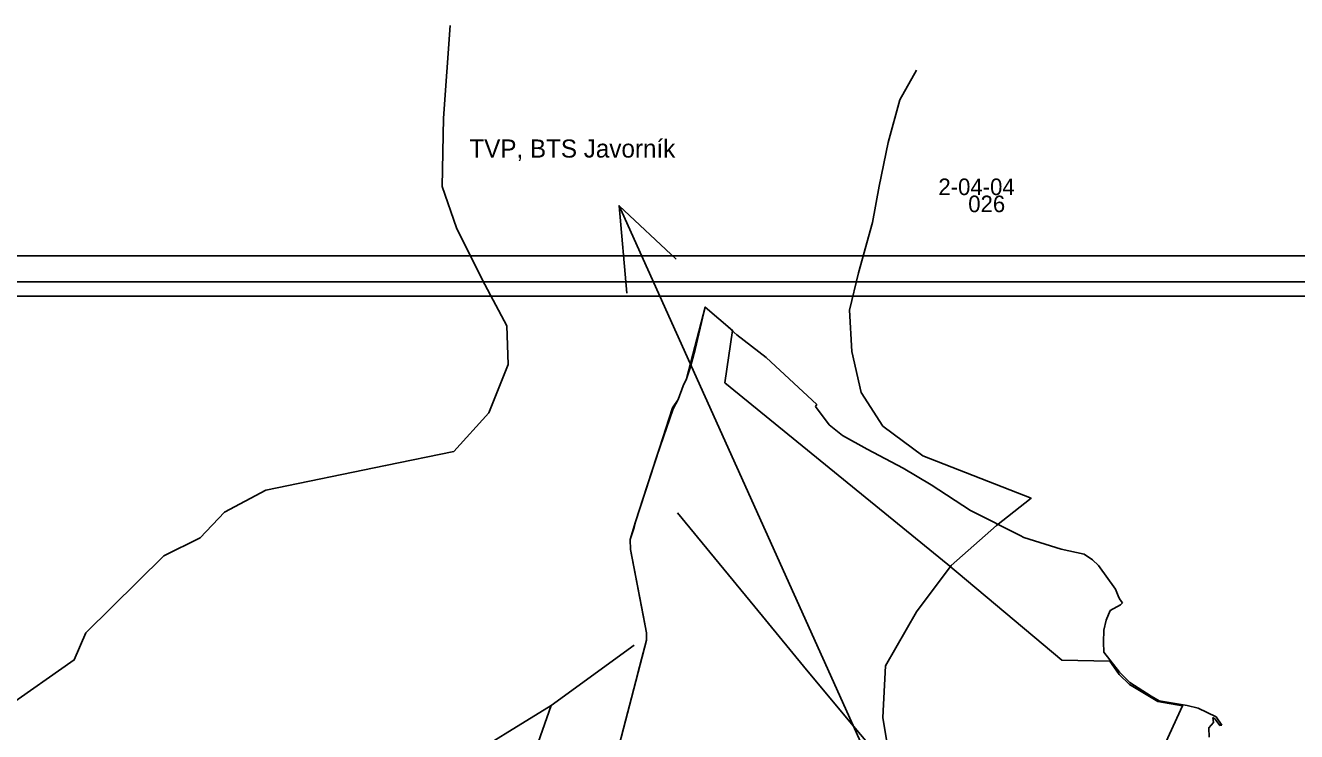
# Model space of a CAD drawing. Extents: x -557103 to -548162, y -1041918 to -1033974.
# Drawn here: x -554667 to -552210, y -1035524 to -1034159 of the extents above; entities that cross this region are included whole.
import ezdxf

# ---------------------------------------------------------------- set-up
doc = ezdxf.new("R2010")
doc.units = 0
for name, color, linetype in [('body1', 7, 'Continuous'), ('body3', 7, 'Continuous'), ('Rámeček', 7, 'Continuous'), ('Vrstva 12', 7, 'Continuous'), ('Vrstva 14', 7, 'Continuous'), ('Vrstva 15', 7, 'Continuous'), ('Vrstva 16', 7, 'Continuous'), ('Vrstva 63', 7, 'Continuous'), ('Vrstva 9', 7, 'Continuous')]:
    doc.layers.add(name, color=color, linetype=linetype)

msp = doc.modelspace()

# ---------------------------------------------------------------- linework, layer by layer
at = {"layer": 'body1'}
msp.add_lwpolyline([(-550469.3, -1040018.6), (-555211.6, -1040018.6), (-555211.6, -1034654.7), (-550469.3, -1034654.7)], close=True, dxfattribs=at)
at = {"layer": 'body3'}
for p, q in [((-553352.9, -1034702.9), (-553372.3, -1034785.2)), ((-553292, -1034757.1), (-553352.9, -1034702.9)), ((-553235.4, -1034801), (-553292, -1034757.1)), ((-553372.3, -1034785.2), (-553381.7, -1034818.7)), ((-553137.6, -1034891.8), (-553235.4, -1034801)), ((-553381.7, -1034818.7), (-553389.1, -1034842)), ((-553389.1, -1034842), (-553395.8, -1034855.3)), ((-553395.8, -1034855.3), (-553405.4, -1034882.1)), ((-553416.1, -1034897.8), (-553441.4, -1034976.1)), ((-553405.4, -1034882.1), (-553416.1, -1034897.8)), ((-553139.7, -1034895.2), (-553137.6, -1034891.8)), ((-553113.8, -1034931.1), (-553139.7, -1034895.2)), ((-553088, -1034951.8), (-553113.8, -1034931.1)), ((-553040.2, -1034977.8), (-553088, -1034951.8)), ((-553441.4, -1034976.1), (-553487.7, -1035118.7)), ((-552970.6, -1035014.9), (-553040.2, -1034977.8)), ((-552916.4, -1035047.1), (-552970.6, -1035014.9)), ((-552840.6, -1035096.7), (-552916.4, -1035047.1)), ((-552741.6, -1035146.3), (-552840.6, -1035096.7)), ((-553487.7, -1035118.7), (-553490.7, -1035129.1)), ((-553490.7, -1035129.1), (-553497.9, -1035152.3)), ((-552739.5, -1035147.3), (-552741.6, -1035146.3)), ((-552737.1, -1035148.6), (-552739.5, -1035147.3)), ((-552665, -1035171.2), (-552737.1, -1035148.6)), ((-553497.9, -1035152.3), (-553497.8, -1035171.9)), ((-553497.8, -1035171.9), (-553466.6, -1035332.8)), ((-552620.8, -1035181), (-552665, -1035171.2)), ((-552604.2, -1035191.8), (-552620.8, -1035181)), ((-552592.7, -1035202.9), (-552604.2, -1035191.8)), ((-552560, -1035248.3), (-552592.7, -1035202.9)), ((-552553.3, -1035264.8), (-552560, -1035248.3)), ((-552551.3, -1035269.1), (-552553.3, -1035264.8)), ((-552546.5, -1035274.7), (-552551.3, -1035269.1)), ((-552577.8, -1035308.7), (-552570.4, -1035290.1)), ((-552570.4, -1035290.1), (-552550.7, -1035278.7)), ((-552550.7, -1035278.7), (-552546.5, -1035274.7)), ((-552582.5, -1035328.1), (-552577.8, -1035308.7)), ((-553466.6, -1035332.8), (-553466.8, -1035347.5)), ((-552583.3, -1035350.9), (-552582.5, -1035328.1)), ((-553466.8, -1035347.5), (-553499.5, -1035473.7)), ((-552582.3, -1035370.7), (-552583.3, -1035350.9)), ((-552552.5, -1035408.8), (-552582.3, -1035370.7)), ((-552532.6, -1035429.3), (-552552.5, -1035408.8)), ((-552491.1, -1035455.5), (-552532.6, -1035429.3)), ((-552475.8, -1035464.2), (-552491.1, -1035455.5)), ((-552421.6, -1035473.8), (-552475.8, -1035464.2)), ((-553499.5, -1035473.7), (-553532.1, -1035599.9)), ((-552400.4, -1035478.6), (-552421.6, -1035473.8)), ((-552365.2, -1035495.4), (-552400.4, -1035478.6)), ((-552379.4, -1035516.6), (-552370.7, -1035506.3)), ((-552379.3, -1035535), (-552379.4, -1035516.6)), ((-552370.7, -1035506.3), (-552372, -1035497)), ((-552372, -1035497), (-552367.4, -1035500.1)), ((-552367.4, -1035500.1), (-552358.1, -1035512.3)), ((-552354.5, -1035511.6), (-552365.2, -1035495.4)), ((-552358.1, -1035512.3), (-552354.5, -1035511.6))]:
    msp.add_line(p, q, dxfattribs=at)
at = {"layer": 'Rámeček'}
for points in [[(-555307.9, -1039662.1), (-550042, -1039662.1), (-550042, -1034604.4), (-555307.9, -1034604.4)], [(-555307.9, -1034604.4), (-548161.9, -1034604.4), (-548161.9, -1039661.8), (-555307.9, -1039661.8)]]:
    msp.add_lwpolyline(points, close=True, dxfattribs=at)
at = {"layer": 'Vrstva 12'}
for points in [[(-553490.5, -1035357.1), (-553650.7, -1035473.7)], [(-554209.3, -1035817.9), (-553650.7, -1035473.7), (-553790.3, -1035869.7), (-554007.5, -1036074.1)]]:
    msp.add_lwpolyline(points, dxfattribs=at)
at = {"layer": 'Vrstva 14'}
msp.add_line((-553519.6, -1034507.2), (-553409.2, -1034610.3), dxfattribs=at)
msp.add_lwpolyline([(-551661.8, -1038633.9), (-553519.6, -1034507.2), (-553504.9, -1034676.5)], dxfattribs=at)
at = {"layer": 'Vrstva 15'}
msp.add_lwpolyline([(-552535.4, -1036170.7), (-552615.2, -1036071.2), (-552694.3, -1035972.7), (-552775.3, -1035871.8), (-552858.1, -1035768.8), (-552941.7, -1035664.7), (-552998.6, -1035594.1), (-553079.8, -1035497.3), (-553163.3, -1035397.2), (-553257.3, -1035282.8), (-553335.2, -1035188.3), (-553406.8, -1035101.3)], dxfattribs=at)
at = {"layer": 'Vrstva 16'}
for points in [[(-554704.8, -1035477.7), (-554572.8, -1035385.5), (-554550.4, -1035333.2), (-554399.4, -1035184.1), (-554329.6, -1035149.2), (-554282.3, -1035099.4), (-554202.6, -1035057), (-553970.9, -1035009.6), (-553838.8, -1034982.2), (-553771.6, -1034907.4), (-553734.2, -1034814.2), (-553736.7, -1034739.4), (-553784, -1034649.7), (-553833.9, -1034550), (-553861.3, -1034470.2), (-553858.8, -1034338.1), (-553846.3, -1034158.7)], [(-552944.8, -1034245.4), (-552977.2, -1034302.7), (-552999.6, -1034385), (-553017, -1034469.7), (-553029.5, -1034539.5), (-553056.9, -1034636.7), (-553074.4, -1034709), (-553069.4, -1034788.8), (-553051.9, -1034868.6), (-553009.6, -1034933.4), (-552932.3, -1034990.7), (-552723.1, -1035072.9), (-552790.3, -1035125.3), (-552877.5, -1035202.6), (-552944.8, -1035292.3), (-553004.6, -1035397), (-553009.6, -1035496.7), (-553002.1, -1035544)]]:
    msp.add_lwpolyline(points, dxfattribs=at)
at = {"layer": 'Vrstva 63'}
msp.add_lwpolyline([(-550519.3, -1039635.9), (-556362.3, -1039635.9), (-556362.3, -1034682.3), (-550519.3, -1034682.3)], close=True, dxfattribs=at)
at = {"layer": 'Vrstva 9'}
msp.add_lwpolyline([(-552484.1, -1035591), (-552430.3, -1035474.1), (-552478.3, -1035465.8), (-552533, -1035433), (-552553.2, -1035413.3), (-552571.1, -1035387.6), (-552664, -1035385.7), (-552884, -1035200.7), (-553315, -1034849.5), (-553300.2, -1034748.3), (-553352.9, -1034703.1), (-553389.1, -1034842), (-553395.8, -1034855.3), (-553405.4, -1034882.1), (-553415.3, -1034899.7), (-553446.3, -1034991.2), (-553473.4, -1035074.7), (-553487.7, -1035118.7), (-553497.9, -1035152.3), (-553497.8, -1035171.9), (-553473.2, -1035298.8), (-553466.6, -1035332.8), (-553466.8, -1035347.5), (-553476.2, -1035383.8), (-553483.9, -1035413.5), (-553499.5, -1035473.7), (-553509.5, -1035512.6), (-553521.9, -1035560.3)], dxfattribs=at)

# ---------------------------------------------------------------- texts
at = {"layer": 'Vrstva 15'}
msp.add_text('TVP, BTS Javorník', height=35, dxfattribs=at).set_placement((-553808.9, -1034414.2))
at = {"layer": 'Vrstva 16'}
for s, p in [('2-04-04', (-552902.4, -1034486.7)), ('026', (-552844.7, -1034519.7))]:
    msp.add_text(s, height=32, dxfattribs=at).set_placement(p)

doc.saveas('drawing.dxf')
